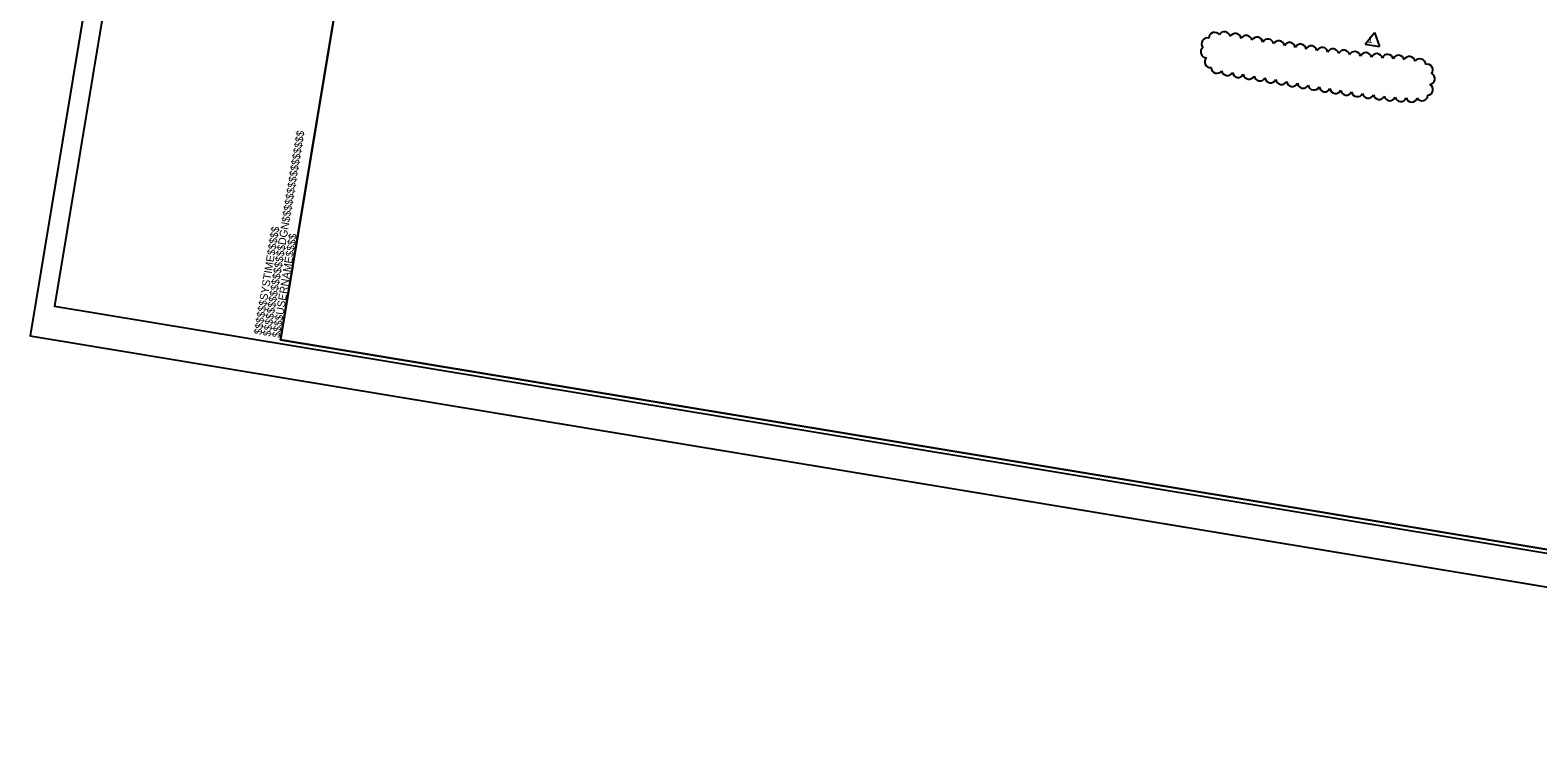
# Model space of a CAD drawing. Extents: x 2191153 to 2193185, y 85349 to 86740.
# Drawn here: x 2191153 to 2192169, y 85379 to 85861 of the extents above; entities that cross this region are included whole.
import ezdxf

# ---------------------------------------------------------------- set-up
doc = ezdxf.new("R2010")
doc.units = 0
for name, color, linetype in [('CTL Primary Horizontal Cogo Comment', 7, 'Continuous'), ('CTL Primary Horizontal Cogo Elevation', 7, 'Continuous'), ('CTL Primary Horizontal Cogo Number', 7, 'Continuous'), ('Exist Other Culture Sign', 7, 'Continuous'), ('Exist Utilities Other Traffic Signal Box CELL', 7, 'Continuous'), ('Old_Level_6', 7, 'Continuous')]:
    doc.layers.add(name, color=color, linetype=linetype)

msp = doc.modelspace()

# ---------------------------------------------------------------- linework, layer by layer
at = {"layer": 'CTL Primary Horizontal Cogo Comment'}
for p, q in [((2191332.5, 86739.7), (2191152.6, 85654.5)), ((2191152.6, 85654.5), (2192814, 85379.2))]:
    msp.add_line(p, q, dxfattribs=at)
at = {"layer": 'CTL Primary Horizontal Cogo Elevation'}
msp.add_lwpolyline([(2192993.8, 86464.4), (2191332.5, 86739.7), (2191152.6, 85654.5), (2192814, 85379.2)], close=True, dxfattribs=at)
at = {"layer": 'CTL Primary Horizontal Cogo Number'}
msp.add_lwpolyline([(2192985.7, 86443), (2191341.6, 86715.4), (2191169.1, 85674.5), (2192813.2, 85402.1)], close=True, dxfattribs=at)
at = {"layer": 'Exist Other Culture Sign'}
msp.add_lwpolyline([(2192972.9, 86442.5), (2191493.1, 86687.7), (2191321.5, 85651.8), (2192801.3, 85406.6)], close=True, dxfattribs=at)
at = {"layer": 'Exist Utilities Other Traffic Signal Box CELL'}
msp.add_lwpolyline([(2192560.7, 86120.9), (2192910.1, 86063), (2192813.6, 85481), (2192809.4, 85455.3), (2192553.7, 85497.7), (2192545.6, 85449), (2191321.5, 85651.8), (2191478.6, 86600.1), (2192434, 86441.8)], close=True, dxfattribs=at)
at = {"layer": 'Old_Level_6'}
for p, q in [((2192052.5, 85851.3), (2192058.9, 85859.2)), ((2192058.9, 85859.2), (2192062.3, 85849.7)), ((2192052.5, 85851.3), (2192062.3, 85849.7))]:
    msp.add_line(p, q, dxfattribs=at)
for centre, start, end in [((2191946.2, 85851.6), 75.1249, 220.1249), ((2191951.1, 85855.3), 34.1318, 179.1318), ((2191957.8, 85855.8), 8.0917, 153.0917), ((2191965.1, 85854.6), 8.0917, 153.0917), ((2191972.4, 85853.3), 8.0917, 153.0917), ((2191979.7, 85852.1), 8.0917, 153.0917), ((2191987, 85850.9), 8.0917, 153.0917), ((2191994.3, 85849.7), 8.1344, 153.1344), ((2192001.6, 85848.5), 8.4102, 153.4102), ((2191945.6, 85846), 126.8837, 271.8837), ((2191948.3, 85839.3), 131.4604, 276.4604), ((2192008.9, 85847.4), 8.7485, 153.7485), ((2192016.2, 85846.3), 9.1245, 154.1245), ((2192023.6, 85845.2), 9.5456, 154.5456), ((2192030.9, 85844.2), 10.0218, 155.0218), ((2192038.3, 85843.3), 10.5659, 155.5659), ((2192045.6, 85842.4), 11.1957, 156.1957), ((2192053, 85841.7), 11.936, 156.936), ((2192060.4, 85841), 12.8231, 157.8231), ((2192067.8, 85840.5), 13.8333, 158.8333), ((2192075.1, 85839.9), 12.5412, 157.5412), ((2192082.4, 85839.1), 8.8487, 153.8487), ((2191952.6, 85835.5), 181.4201, 326.4201), ((2191959.7, 85833.9), 188.0917, 333.0917), ((2191967, 85832.7), 188.0917, 333.0917), ((2192089.5, 85837.5), 0.8102, 145.8102), ((2192094.4, 85833.8), 320.8744, 105.8744), ((2191974.3, 85831.5), 188.0917, 333.0917), ((2191981.6, 85830.3), 188.0917, 333.0917), ((2191988.9, 85829.1), 188.0917, 333.0917), ((2191996.2, 85827.9), 188.0917, 333.0917), ((2192003.5, 85826.6), 188.0917, 333.0917), ((2192010.8, 85825.4), 188.0917, 333.0917), ((2192018.1, 85824.2), 188.0917, 333.0917), ((2192025.4, 85823), 188.2376, 333.2376), ((2192094.4, 85820.6), 276.7402, 61.7402), ((2192095.7, 85827.9), 278.0917, 63.0917), ((2192032.7, 85821.9), 188.5636, 333.5636), ((2192040, 85820.7), 188.9536, 333.9536), ((2192047.3, 85819.7), 189.4317, 334.4317), ((2192054.6, 85818.7), 190.0371, 335.0371), ((2192062, 85817.8), 190.8382, 335.8382), ((2192069.3, 85817), 191.97, 336.97), ((2192076.6, 85816.4), 193.7488, 338.7488), ((2192084, 85816.1), 197.1967, 342.1967), ((2192090.9, 85817), 211.9324, 356.9324)]:
    msp.add_arc(centre, 3.88, start, end, dxfattribs=at)

# ---------------------------------------------------------------- texts
at = {"layer": 'Exist Other Culture Sign'}
for s, p in [('$$$$$$$$$$$$$$$$DGN$$$$$$$$$$$$$$$$', (2191314.6, 85653.8)), ('$$$$$$SYSTIME$$$$$', (2191308.6, 85655)), ('$$$$USERNAME$$$$', (2191320.8, 85652.9))]:
    msp.add_text(s, height=5.25, rotation=80.5917, dxfattribs=at).set_placement(p)
at = {"layer": 'Old_Level_6'}
msp.add_text(' 1', height=4.5, rotation=350.5917, dxfattribs=at).set_placement((2192052.4, 85852.7))

doc.saveas('drawing.dxf')
